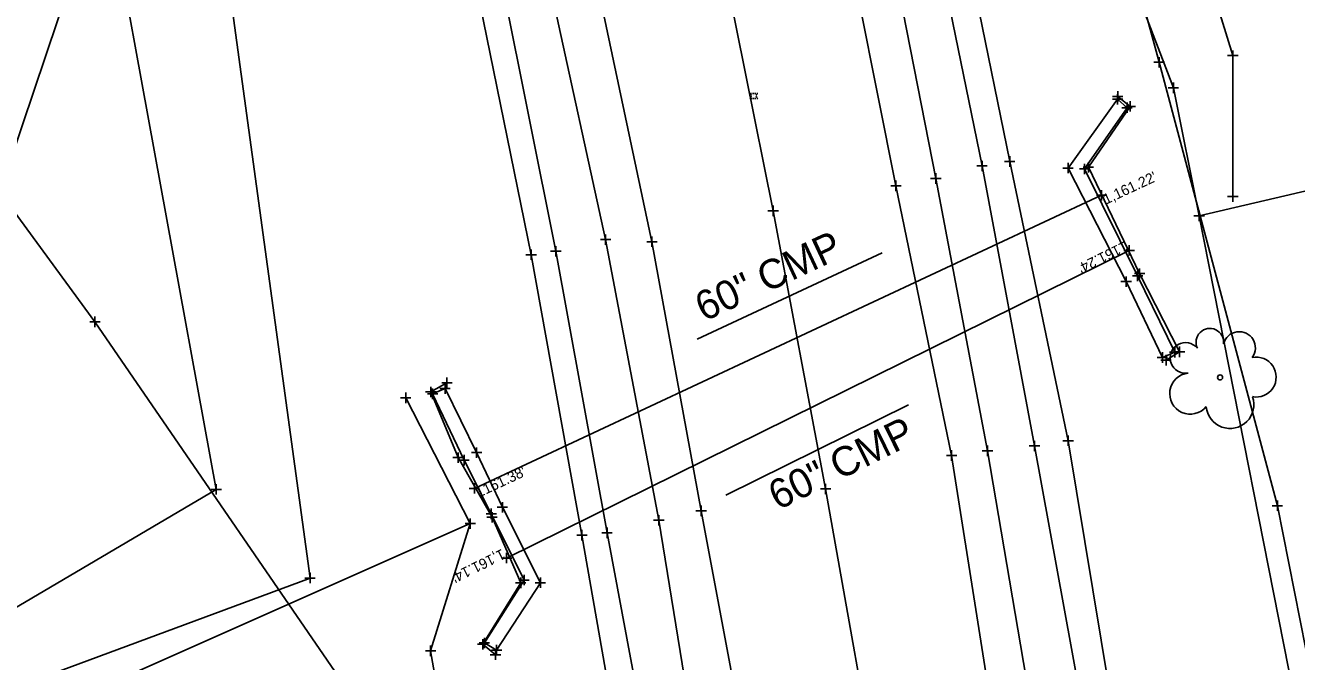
# Model space of a CAD drawing. Extents: x 2324380 to 2325559, y 691096 to 693386.
# Drawn here: x 2325086.8 to 2325208.5, y 691791.1 to 691852 of the extents above; entities that cross this region are included whole.
import ezdxf

# ---------------------------------------------------------------- set-up
doc = ezdxf.new("R2010")
doc.units = 0
for name, color, linetype in [('DR_X_Elev_Flow', 7, 'Continuous'), ('DR_X_Headwall', 7, 'Continuous'), ('DR_X_Storm_Sewer', 7, 'Continuous'), ('DR_X_Text', 7, 'Continuous'), ('PM_X_Cells', 7, 'Continuous'), ('PM_X_CL_Double_Solid', 7, 'Continuous'), ('PM_X_Transverse_Line', 7, 'Continuous'), ('PV_X_COP', 7, 'Continuous'), ('PV_X_EOP', 7, 'Continuous'), ('PV_X_Shoulder_Aggregate', 7, 'Continuous'), ('RD_X_GR_Lt', 7, 'Continuous'), ('RD_X_GR_Rt', 7, 'Continuous'), ('SC_Scratch1', 7, 'Continuous'), ('SV_X_Break_Lines', 7, 'Continuous'), ('SV_X_Shot_Marker', 7, 'Continuous'), ('SV_X_Terrain_Boundary', 7, 'Continuous'), ('SV_X_Toe_of_Slope', 7, 'Continuous'), ('SV_X_Top_of_Bank', 7, 'Continuous'), ('UT_X_Gas', 7, 'Continuous'), ('UT_X_Water', 7, 'Continuous'), ('VG_X_Cells', 7, 'Continuous')]:
    doc.layers.add(name, color=color, linetype=linetype)

msp = doc.modelspace()

# ---------------------------------------------------------------- linework, layer by layer
at = {"layer": 'DR_X_Elev_Flow'}
for p, q in [((2325189.3, 691835.71), (2325190.3, 691835.71)), ((2325189.8, 691836.21), (2325189.8, 691835.21)), ((2325189.8, 691835.71), (2325189.8, 691835.71)), ((2325192.44, 691830.94), (2325192.44, 691829.94)), ((2325191.94, 691830.44), (2325192.94, 691830.44)), ((2325192.44, 691830.44), (2325192.44, 691830.44)), ((2325129.27, 691807.67), (2325130.27, 691807.67)), ((2325129.77, 691808.17), (2325129.77, 691807.17)), ((2325129.77, 691807.67), (2325129.77, 691807.67)), ((2325132.85, 691801.51), (2325132.85, 691800.51)), ((2325132.35, 691801.01), (2325133.35, 691801.01)), ((2325132.85, 691801.01), (2325132.85, 691801.01))]:
    msp.add_line(p, q, dxfattribs=at)
at = {"layer": 'DR_X_Headwall'}
for points in [[(2325192.24, 691844.08), (2325191.33, 691844.89), (2325186.59, 691838.31), (2325192.15, 691827.45), (2325195.62, 691820.19)], [(2325192.24, 691844.08), (2325188.17, 691838.23), (2325193.25, 691827.99), (2325196.81, 691820.7), (2325195.62, 691820.19)], [(2325130.73, 691792.88), (2325134.52, 691798.9), (2325131.39, 691805.23), (2325128.78, 691810.37), (2325125.77, 691816.72), (2325126.96, 691817.22)], [(2325130.73, 691792.88), (2325131.9, 691792.2), (2325136.09, 691798.65), (2325132.45, 691805.86), (2325129.98, 691811.09), (2325126.96, 691817.22)]]:
    msp.add_lwpolyline(points, dxfattribs=at)
at = {"layer": 'DR_X_Storm_Sewer'}
for p, q in [((2325129.77, 691807.67), (2325189.8, 691835.71)), ((2325192.44, 691830.44), (2325132.85, 691801.01))]:
    msp.add_line(p, q, dxfattribs=at)
at = {"layer": 'DR_X_Text'}
for p, q in [((2325168.79, 691830.2), (2325151.1, 691821.94)), ((2325153.83, 691807.02), (2325171.33, 691815.67))]:
    msp.add_line(p, q, dxfattribs=at)
at = {"layer": 'PM_X_Cells'}
for p, q in [((2325156.12, 691845.45), (2325156.22, 691845.45)), ((2325156.29, 691845.45), (2325156.39, 691845.45)), ((2325156.46, 691845.45), (2325156.56, 691845.45)), ((2325156.51, 691845.21), (2325156.51, 691845.21)), ((2325156.62, 691845.45), (2325156.72, 691845.45)), ((2325156.79, 691845.45), (2325156.89, 691845.45)), ((2325156.12, 691844.96), (2325156.22, 691844.96)), ((2325156.29, 691844.96), (2325156.39, 691844.96)), ((2325156.46, 691844.96), (2325156.56, 691844.96)), ((2325156.62, 691844.96), (2325156.72, 691844.96)), ((2325156.79, 691844.96), (2325156.89, 691844.96))]:
    msp.add_line(p, q, dxfattribs=at)
for centre, start, end in [((2325155.97, 691845.21), 42.0847, 58.0262), ((2325155.97, 691845.21), 18.8878, 34.8207), ((2325155.97, 691845.21), 348.3904, 11.6202), ((2325157.04, 691845.21), 168.3816, 191.6091), ((2325157.04, 691845.21), 145.1782, 161.1098), ((2325157.04, 691845.21), 121.9738, 137.9163), ((2325155.97, 691845.21), 301.9738, 317.9205), ((2325155.97, 691845.21), 325.1782, 341.1111), ((2325157.04, 691845.21), 198.8872, 214.8207), ((2325157.04, 691845.21), 222.0817, 238.0262)]:
    msp.add_arc(centre, 0.288, start, end, dxfattribs=at)
at = {"layer": 'PM_X_CL_Double_Solid'}
msp.add_lwpolyline([(2325203.69, 691549.65), (2325199.81, 691578.72), (2325195.9, 691603.62), (2325192.28, 691631.74), (2325187.11, 691666.48), (2325182.79, 691692.39), (2325178.74, 691718.23), (2325173.96, 691747.27), (2325169.08, 691775.55), (2325163.39, 691807.62), (2325158.37, 691834.22), (2325153.07, 691860.53), (2325147.82, 691885.48), (2325142.33, 691910.37), (2325135.95, 691937.62), (2325128.86, 691967.59), (2325122.12, 691994.31), (2325114.33, 692023.68), (2325108.45, 692046.03), (2325104.94, 692058.15)], dxfattribs=at)
at = {"layer": 'PM_X_Transverse_Line'}
for points in [[(2325208.03, 691604.62), (2325194.77, 691694.59), (2325190.22, 691721.35), (2325186.04, 691748.47), (2325180.66, 691777.72), (2325175.44, 691810.81), (2325170.12, 691836.61), (2325164.91, 691862.73), (2325159.59, 691887.99), (2325154.32, 691913.69), (2325148, 691940.38), (2325141.01, 691970.75), (2325134.25, 691997.6), (2325126.61, 692026.24), (2325119.99, 692049.57), (2325112.24, 692077.64)], [(2325192.19, 691548.44), (2325188.05, 691576.64), (2325184.35, 691601.09), (2325180.61, 691630.23), (2325175.41, 691665.27), (2325167.04, 691716.76), (2325162.47, 691745.62), (2325157.37, 691774.04), (2325151.47, 691805.52), (2325146.76, 691831.27), (2325141.02, 691858.38), (2325136.15, 691882.66), (2325130.6, 691908), (2325124.67, 691934.37), (2325117.5, 691964.78), (2325110.75, 691991.5), (2325102.89, 692021.66), (2325098.58, 692037.21)]]:
    msp.add_lwpolyline(points, dxfattribs=at)
at = {"layer": 'PV_X_COP'}
msp.add_lwpolyline([(2325203.69, 691549.65), (2325199.81, 691578.72), (2325195.9, 691603.62), (2325192.28, 691631.74), (2325187.11, 691666.48), (2325182.79, 691692.39), (2325178.74, 691718.23), (2325173.96, 691747.27), (2325169.08, 691775.55), (2325163.39, 691807.62), (2325158.37, 691834.22), (2325153.07, 691860.53), (2325147.82, 691885.48), (2325142.33, 691910.37), (2325135.95, 691937.62), (2325128.86, 691967.59), (2325122.12, 691994.31), (2325114.33, 692023.68), (2325108.45, 692046.03), (2325099.34, 692075.66)], dxfattribs=at)
at = {"layer": 'PV_X_EOP'}
for p, q in [((2325142.33, 691831.47), (2325136.62, 691857.51)), ((2325147.42, 691804.62), (2325142.33, 691831.47)), ((2325152.64, 691772.64), (2325147.42, 691804.62))]:
    msp.add_line(p, q, dxfattribs=at)
msp.add_lwpolyline([(2325211.92, 691605.39), (2325210.37, 691618.55), (2325213.96, 691624.8), (2325210.03, 691657.83), (2325203.56, 691662.57), (2325202.33, 691668.93), (2325198.24, 691695.48), (2325193.91, 691721.99), (2325189.38, 691749.91), (2325184.43, 691778.63), (2325178.88, 691811.26), (2325173.94, 691837.31), (2325168.71, 691863.96), (2325163.82, 691888.36), (2325158.39, 691913.65), (2325152.29, 691941.35), (2325145.12, 691971.33), (2325138.19, 691997.21), (2325140.74, 692005.58), (2325134.93, 692029.17), (2325130.4, 692046.73), (2325123.25, 692051.46), (2325115.82, 692078.51)], dxfattribs=at)
at = {"layer": 'PV_X_Shoulder_Aggregate'}
for p, q in [((2325181.01, 691838.94), (2325175.46, 691866.14)), ((2325186.6, 691812.23), (2325181.01, 691838.94)), ((2325191.94, 691780.01), (2325186.6, 691812.23))]:
    msp.add_line(p, q, dxfattribs=at)
msp.add_lwpolyline([(2325170.4, 691645.86), (2325170.09, 691649.23), (2325166.75, 691649.33), (2325163.95, 691663.81), (2325159.46, 691688.82), (2325155.24, 691715.43), (2325150.26, 691742.78), (2325145.57, 691771.72), (2325140.06, 691803.19), (2325135.21, 691830.02), (2325129.98, 691855.68), (2325124.5, 691880.26), (2325119.34, 691905.48), (2325112.99, 691932.07), (2325105.49, 691961.94), (2325098.55, 691989.12), (2325091.91, 692018.77), (2325090.18, 692026), (2325093.94, 692028.55)], dxfattribs=at)
at = {"layer": 'RD_X_GR_Lt'}
msp.add_lwpolyline([(2325168.31, 691650.15), (2325165.91, 691664.32), (2325160.24, 691688.12), (2325157.53, 691715.74), (2325153.07, 691743.32), (2325148.21, 691772.69), (2325142.47, 691803.42), (2325137.57, 691830.35), (2325132.48, 691855.68), (2325127.08, 691880.89), (2325121.34, 691906.57), (2325115.7, 691932.5), (2325101.27, 691989.61), (2325092.98, 692018.84), (2325091.76, 692024.72)], dxfattribs=at)
at = {"layer": 'RD_X_GR_Rt'}
for p, q in [((2325178.36, 691838.51), (2325172.74, 691866.14)), ((2325183.38, 691811.73), (2325178.36, 691838.51)), ((2325189.2, 691779.88), (2325183.38, 691811.73))]:
    msp.add_line(p, q, dxfattribs=at)
at = {"layer": 'SV_X_Break_Lines'}
for points in [[(2325191.34, 691845.16), (2325192.53, 691844.21), (2325188.54, 691838.39), (2325193.44, 691828.21), (2325197.27, 691820.73), (2325195.97, 691819.94)], [(2325131.79, 691791.76), (2325130.58, 691792.76), (2325134.2, 691798.64), (2325131.46, 691804.91), (2325128.22, 691810.61), (2325125.6, 691816.9), (2325127.14, 691817.77)]]:
    msp.add_lwpolyline(points, dxfattribs=at)
at = {"layer": 'SV_X_Shot_Marker'}
for p, q in [((2325195.31, 691848.93), (2325195.31, 691847.93)), ((2325201.86, 691849.07), (2325202.86, 691849.07)), ((2325202.36, 691849.57), (2325202.36, 691848.57)), ((2325202.36, 691849.07), (2325202.36, 691849.07)), ((2325194.81, 691848.43), (2325195.81, 691848.43)), ((2325195.31, 691848.43), (2325195.31, 691848.43)), ((2325196.67, 691846.49), (2325196.67, 691845.49)), ((2325190.84, 691845.16), (2325191.84, 691845.16)), ((2325191.33, 691845.39), (2325191.33, 691844.39)), ((2325191.34, 691845.66), (2325191.34, 691844.66)), ((2325191.34, 691845.16), (2325191.34, 691845.16)), ((2325196.17, 691845.99), (2325197.17, 691845.99)), ((2325196.67, 691845.99), (2325196.67, 691845.99)), ((2325190.83, 691844.89), (2325191.83, 691844.89)), ((2325191.33, 691844.89), (2325191.33, 691844.89)), ((2325191.74, 691844.08), (2325192.74, 691844.08)), ((2325191.74, 691844.08), (2325192.74, 691844.08)), ((2325192.03, 691844.21), (2325193.03, 691844.21)), ((2325192.24, 691844.58), (2325192.24, 691843.58)), ((2325192.24, 691844.58), (2325192.24, 691843.58)), ((2325192.24, 691844.08), (2325192.24, 691844.08)), ((2325192.24, 691844.08), (2325192.24, 691844.08)), ((2325192.53, 691844.71), (2325192.53, 691843.71)), ((2325192.53, 691844.21), (2325192.53, 691844.21)), ((2325181.01, 691839.44), (2325181.01, 691838.44)), ((2325177.86, 691838.51), (2325178.86, 691838.51)), ((2325178.36, 691839.01), (2325178.36, 691838.01)), ((2325178.36, 691838.51), (2325178.36, 691838.51)), ((2325180.51, 691838.94), (2325181.51, 691838.94)), ((2325181.01, 691838.94), (2325181.01, 691838.94)), ((2325186.09, 691838.31), (2325187.09, 691838.31)), ((2325186.59, 691838.81), (2325186.59, 691837.81)), ((2325186.59, 691838.31), (2325186.59, 691838.31)), ((2325187.67, 691838.23), (2325188.67, 691838.23)), ((2325188.04, 691838.39), (2325189.04, 691838.39)), ((2325188.17, 691838.73), (2325188.17, 691837.73)), ((2325188.17, 691838.23), (2325188.17, 691838.23)), ((2325188.54, 691838.89), (2325188.54, 691837.89)), ((2325188.54, 691838.39), (2325188.54, 691838.39)), ((2325170.12, 691837.11), (2325170.12, 691836.11)), ((2325173.44, 691837.31), (2325174.44, 691837.31)), ((2325173.94, 691837.81), (2325173.94, 691836.81)), ((2325173.94, 691837.31), (2325173.94, 691837.31)), ((2325169.62, 691836.61), (2325170.62, 691836.61)), ((2325170.12, 691836.61), (2325170.12, 691836.61)), ((2325201.86, 691835.59), (2325202.86, 691835.59)), ((2325202.36, 691836.09), (2325202.36, 691835.09)), ((2325202.36, 691835.59), (2325202.36, 691835.59)), ((2325157.87, 691834.22), (2325158.87, 691834.22)), ((2325157.87, 691834.22), (2325158.87, 691834.22)), ((2325158.37, 691834.72), (2325158.37, 691833.72)), ((2325158.37, 691834.72), (2325158.37, 691833.72)), ((2325158.37, 691834.22), (2325158.37, 691834.22)), ((2325158.37, 691834.22), (2325158.37, 691834.22)), ((2325199.14, 691834.23), (2325199.14, 691833.23)), ((2325199.14, 691834.23), (2325199.14, 691833.23)), ((2325198.64, 691833.73), (2325199.64, 691833.73)), ((2325198.64, 691833.73), (2325199.64, 691833.73)), ((2325199.14, 691833.73), (2325199.14, 691833.73)), ((2325199.14, 691833.73), (2325199.14, 691833.73)), ((2325142.33, 691831.97), (2325142.33, 691830.97)), ((2325146.76, 691831.77), (2325146.76, 691830.77)), ((2325137.57, 691830.85), (2325137.57, 691829.85)), ((2325141.83, 691831.47), (2325142.83, 691831.47)), ((2325142.33, 691831.47), (2325142.33, 691831.47)), ((2325146.26, 691831.27), (2325147.26, 691831.27)), ((2325146.76, 691831.27), (2325146.76, 691831.27)), ((2325134.71, 691830.02), (2325135.71, 691830.02)), ((2325135.21, 691830.52), (2325135.21, 691829.52)), ((2325135.21, 691830.02), (2325135.21, 691830.02)), ((2325137.07, 691830.35), (2325138.07, 691830.35)), ((2325137.57, 691830.35), (2325137.57, 691830.35)), ((2325192.94, 691828.21), (2325193.94, 691828.21)), ((2325193.25, 691828.49), (2325193.25, 691827.49)), ((2325193.44, 691828.71), (2325193.44, 691827.71)), ((2325193.44, 691828.21), (2325193.44, 691828.21)), ((2325191.65, 691827.45), (2325192.65, 691827.45)), ((2325192.15, 691827.95), (2325192.15, 691826.95)), ((2325192.15, 691827.45), (2325192.15, 691827.45)), ((2325192.75, 691827.99), (2325193.75, 691827.99)), ((2325193.25, 691827.99), (2325193.25, 691827.99)), ((2325092.96, 691823.6), (2325093.96, 691823.6)), ((2325093.46, 691824.1), (2325093.46, 691823.1)), ((2325093.46, 691823.6), (2325093.46, 691823.6)), ((2325196.81, 691821.2), (2325196.81, 691820.2)), ((2325197.27, 691821.23), (2325197.27, 691820.23)), ((2325195.12, 691820.19), (2325196.12, 691820.19)), ((2325195.12, 691820.19), (2325196.12, 691820.19)), ((2325195.47, 691819.94), (2325196.47, 691819.94)), ((2325195.62, 691820.69), (2325195.62, 691819.69)), ((2325195.62, 691820.69), (2325195.62, 691819.69)), ((2325195.62, 691820.19), (2325195.62, 691820.19)), ((2325195.62, 691820.19), (2325195.62, 691820.19)), ((2325195.97, 691820.44), (2325195.97, 691819.44)), ((2325195.97, 691819.94), (2325195.97, 691819.94)), ((2325196.31, 691820.7), (2325197.31, 691820.7)), ((2325196.77, 691820.73), (2325197.77, 691820.73)), ((2325196.81, 691820.7), (2325196.81, 691820.7)), ((2325197.27, 691820.73), (2325197.27, 691820.73)), ((2325125.6, 691817.4), (2325125.6, 691816.4)), ((2325125.77, 691817.22), (2325125.77, 691816.22)), ((2325126.46, 691817.22), (2325127.46, 691817.22)), ((2325126.46, 691817.22), (2325127.46, 691817.22)), ((2325126.64, 691817.77), (2325127.64, 691817.77)), ((2325126.96, 691817.72), (2325126.96, 691816.72)), ((2325126.96, 691817.72), (2325126.96, 691816.72)), ((2325126.96, 691817.22), (2325126.96, 691817.22)), ((2325126.96, 691817.22), (2325126.96, 691817.22)), ((2325127.14, 691818.27), (2325127.14, 691817.27)), ((2325127.14, 691817.77), (2325127.14, 691817.77)), ((2325122.7, 691816.33), (2325123.7, 691816.33)), ((2325123.2, 691816.83), (2325123.2, 691815.83)), ((2325123.2, 691816.33), (2325123.2, 691816.33)), ((2325125.1, 691816.9), (2325126.1, 691816.9)), ((2325125.27, 691816.72), (2325126.27, 691816.72)), ((2325125.6, 691816.9), (2325125.6, 691816.9)), ((2325125.77, 691816.72), (2325125.77, 691816.72)), ((2325186.6, 691812.73), (2325186.6, 691811.73)), ((2325128.22, 691811.11), (2325128.22, 691810.11)), ((2325129.48, 691811.09), (2325130.48, 691811.09)), ((2325129.98, 691811.59), (2325129.98, 691810.59)), ((2325129.98, 691811.09), (2325129.98, 691811.09)), ((2325175.44, 691811.31), (2325175.44, 691810.31)), ((2325178.38, 691811.26), (2325179.38, 691811.26)), ((2325178.88, 691811.76), (2325178.88, 691810.76)), ((2325178.88, 691811.26), (2325178.88, 691811.26)), ((2325182.88, 691811.73), (2325183.88, 691811.73)), ((2325183.38, 691812.23), (2325183.38, 691811.23)), ((2325183.38, 691811.73), (2325183.38, 691811.73)), ((2325186.1, 691812.23), (2325187.1, 691812.23)), ((2325186.6, 691812.23), (2325186.6, 691812.23)), ((2325127.72, 691810.61), (2325128.72, 691810.61)), ((2325128.22, 691810.61), (2325128.22, 691810.61)), ((2325128.28, 691810.37), (2325129.28, 691810.37)), ((2325128.78, 691810.87), (2325128.78, 691809.87)), ((2325128.78, 691810.37), (2325128.78, 691810.37)), ((2325174.94, 691810.81), (2325175.94, 691810.81)), ((2325175.44, 691810.81), (2325175.44, 691810.81)), ((2325104.57, 691807.57), (2325105.57, 691807.57)), ((2325105.07, 691808.07), (2325105.07, 691807.07)), ((2325105.07, 691807.57), (2325105.07, 691807.57)), ((2325162.89, 691807.62), (2325163.89, 691807.62)), ((2325162.89, 691807.62), (2325163.89, 691807.62)), ((2325163.39, 691808.12), (2325163.39, 691807.12)), ((2325163.39, 691808.12), (2325163.39, 691807.12)), ((2325163.39, 691807.62), (2325163.39, 691807.62)), ((2325163.39, 691807.62), (2325163.39, 691807.62)), ((2325132.45, 691806.36), (2325132.45, 691805.36)), ((2325206.62, 691806.51), (2325206.62, 691805.51)), ((2325130.89, 691805.23), (2325131.89, 691805.23)), ((2325131.39, 691805.73), (2325131.39, 691804.73)), ((2325131.39, 691805.23), (2325131.39, 691805.23)), ((2325131.46, 691805.41), (2325131.46, 691804.41)), ((2325131.95, 691805.86), (2325132.95, 691805.86)), ((2325132.45, 691805.86), (2325132.45, 691805.86)), ((2325147.42, 691805.12), (2325147.42, 691804.12)), ((2325150.97, 691805.52), (2325151.97, 691805.52)), ((2325151.47, 691806.02), (2325151.47, 691805.02)), ((2325151.47, 691805.52), (2325151.47, 691805.52)), ((2325206.12, 691806.01), (2325207.12, 691806.01)), ((2325206.62, 691806.01), (2325206.62, 691806.01)), ((2325128.88, 691804.3), (2325129.88, 691804.3)), ((2325128.88, 691804.3), (2325129.88, 691804.3)), ((2325129.38, 691804.8), (2325129.38, 691803.8)), ((2325129.38, 691804.8), (2325129.38, 691803.8)), ((2325129.38, 691804.3), (2325129.38, 691804.3)), ((2325129.38, 691804.3), (2325129.38, 691804.3)), ((2325130.96, 691804.91), (2325131.96, 691804.91)), ((2325131.46, 691804.91), (2325131.46, 691804.91)), ((2325142.47, 691803.92), (2325142.47, 691802.92)), ((2325146.92, 691804.62), (2325147.92, 691804.62)), ((2325147.42, 691804.62), (2325147.42, 691804.62)), ((2325139.56, 691803.19), (2325140.56, 691803.19)), ((2325140.06, 691803.69), (2325140.06, 691802.69)), ((2325140.06, 691803.19), (2325140.06, 691803.19)), ((2325141.97, 691803.42), (2325142.97, 691803.42)), ((2325142.47, 691803.42), (2325142.47, 691803.42)), ((2325113.54, 691799.09), (2325114.54, 691799.09)), ((2325114.04, 691799.59), (2325114.04, 691798.59)), ((2325114.04, 691799.09), (2325114.04, 691799.09)), ((2325134.2, 691799.14), (2325134.2, 691798.14)), ((2325134.52, 691799.4), (2325134.52, 691798.4)), ((2325136.09, 691799.15), (2325136.09, 691798.15)), ((2325133.7, 691798.64), (2325134.7, 691798.64)), ((2325134.02, 691798.9), (2325135.02, 691798.9)), ((2325134.2, 691798.64), (2325134.2, 691798.64)), ((2325134.52, 691798.9), (2325134.52, 691798.9)), ((2325135.59, 691798.65), (2325136.59, 691798.65)), ((2325136.09, 691798.65), (2325136.09, 691798.65)), ((2325130.23, 691792.88), (2325131.23, 691792.88)), ((2325130.23, 691792.88), (2325131.23, 691792.88)), ((2325130.58, 691793.26), (2325130.58, 691792.26)), ((2325130.73, 691793.38), (2325130.73, 691792.38)), ((2325130.73, 691793.38), (2325130.73, 691792.38)), ((2325130.73, 691792.88), (2325130.73, 691792.88)), ((2325130.73, 691792.88), (2325130.73, 691792.88)), ((2325125.08, 691792.13), (2325126.08, 691792.13)), ((2325125.58, 691792.63), (2325125.58, 691791.63)), ((2325125.58, 691792.13), (2325125.58, 691792.13)), ((2325130.08, 691792.76), (2325131.08, 691792.76)), ((2325130.58, 691792.76), (2325130.58, 691792.76)), ((2325131.29, 691791.76), (2325132.29, 691791.76)), ((2325131.4, 691792.2), (2325132.4, 691792.2)), ((2325131.79, 691792.26), (2325131.79, 691791.26)), ((2325131.79, 691791.76), (2325131.79, 691791.76)), ((2325131.9, 691792.7), (2325131.9, 691791.7)), ((2325131.9, 691792.2), (2325131.9, 691792.2))]:
    msp.add_line(p, q, dxfattribs=at)
at = {"layer": 'SV_X_Terrain_Boundary'}
msp.add_lwpolyline([(2325040.39, 692094.78), (2325055.27, 692032.59), (2325083.21, 691968.66), (2325093.87, 691919.58), (2325094.39, 691865.88), (2325067.26, 691785.3), (2324974.04, 691758.93), (2324878.59, 691733.65), (2324786.86, 691712.89), (2324706.59, 691703.47), (2324706.71, 691700.83), (2324706.09, 691698.67)], dxfattribs=at)
at = {"layer": 'SV_X_Toe_of_Slope'}
for points in [[(2325073.01, 692023.97), (2325085.82, 691969.29), (2325098.6, 691921.07), (2325104.84, 691866.44), (2325114.04, 691799.09), (2325069, 691782.4)], [(2325151.72, 692005.8), (2325157.69, 691974.87), (2325176.19, 691918.4), (2325187.81, 691869.15), (2325196.67, 691845.99), (2325199.14, 691833.73)], [(2325151.72, 692005.8), (2325162.71, 691976.55), (2325181.2, 691920.28), (2325195.81, 691870.26), (2325202.36, 691849.07), (2325202.36, 691835.59)], [(2325217.55, 691708.33), (2325209.12, 691783.16), (2325199.14, 691833.73), (2325229.59, 691840.86), (2325259.98, 691849.99)], [(2325129.38, 691804.3), (2325123.2, 691816.33)], [(2325158.56, 691645.64), (2325147.08, 691688.36), (2325134.23, 691743.21), (2325125.58, 691792.13), (2325129.38, 691804.3), (2325075.41, 691780.38)]]:
    msp.add_lwpolyline(points, dxfattribs=at)
at = {"layer": 'SV_X_Top_of_Bank'}
msp.add_lwpolyline([(2325055.27, 692032.59), (2325063.03, 692032.6), (2325067.56, 692023.53), (2325083.21, 691968.66), (2325093.87, 691919.58), (2325094.39, 691865.88), (2325105.07, 691807.57), (2325067.26, 691785.3)], dxfattribs=at)
at = {"layer": 'UT_X_Gas'}
msp.add_lwpolyline([(2324989.07, 691970.86), (2325011.6, 691941.58), (2325048.05, 691885.65), (2325093.46, 691823.6), (2325120.8, 691783.81), (2325138.43, 691746.33), (2325151.4, 691693.8), (2325156.77, 691659.76), (2325167.15, 691600.95), (2325171.48, 691564.26), (2325179.43, 691516.76), (2325185.5, 691470.97), (2325191.97, 691423.91), (2325198.27, 691377.48), (2325205.02, 691332.94), (2325213.79, 691283.13)], dxfattribs=at)
at = {"layer": 'UT_X_Water'}
msp.add_lwpolyline([(2325124.52, 692091.67), (2325134.64, 692057.74), (2325147.68, 692015.89), (2325157.51, 691980.18), (2325171.32, 691933.62), (2325182.7, 691894.58), (2325195.31, 691848.43), (2325206.62, 691806.01), (2325210.43, 691786.81), (2325214.15, 691760.19), (2325217.41, 691715.9), (2325220.6, 691667.67), (2325222.98, 691628.17), (2325224.5, 691603.22), (2325224.97, 691587.75)], dxfattribs=at)
at = {"layer": 'VG_X_Cells'}
msp.add_circle((2325201.14, 691818.29), 0.24, dxfattribs=at)
for centre, radius, start, end in [((2325200.16, 691821.65), 1.32, 354.0047, 205.9741), ((2325202.97, 691821.11), 1.55, 323.83, 165.0376), ((2325197.83, 691820.15), 1.47, 39.0625, 279.5412), ((2325204.6, 691818.32), 1.91, 259.1453, 101.4596), ((2325198.29, 691816.74), 1.97, 96.1722, 320.5737), ((2325202.09, 691815.68), 2.28, 184.9476, 19.4572)]:
    msp.add_arc(centre, radius, start, end, dxfattribs=at)

# ---------------------------------------------------------------- texts
at = {"layer": 'DR_X_Text'}
for rotation, p in [(25.0344, (2325151.75, 691823.59)), (26.2872, (2325158.82, 691805.54))]:
    msp.add_text('60" CMP', height=2.8, rotation=rotation, dxfattribs=at).set_placement(p)
at = {"layer": 'SC_Scratch1'}
for s, rotation, p in [("1,161.22'", 25.0344, (2325190.23, 691834.81)), ("1161.24'", 206.2872, (2325191.99, 691831.34)), ("1161.38'", 25.0344, (2325130.19, 691806.77)), ("1,161.14'", 206.2872, (2325132.4, 691801.91))]:
    msp.add_text(s, height=1, rotation=rotation, dxfattribs=at).set_placement(p)

doc.saveas('drawing.dxf')
